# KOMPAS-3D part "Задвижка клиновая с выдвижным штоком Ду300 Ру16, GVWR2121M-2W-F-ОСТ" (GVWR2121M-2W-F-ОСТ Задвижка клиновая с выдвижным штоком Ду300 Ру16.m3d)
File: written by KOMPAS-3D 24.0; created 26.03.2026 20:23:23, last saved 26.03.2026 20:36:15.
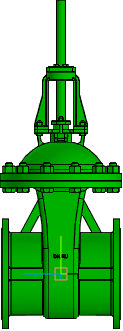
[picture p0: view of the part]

Document properties: Автор: R2D2; Полное имя файла: GVWR2121M-2W-F-ОСТ Задвижка клиновая с видвижным штоком Ду300 Ру16.cdw

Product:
- Part/product: Задвижка клиновая с выдвижным штоком Ду300 Ру16  | designation GVWR2121M-2W-F-ОСТ
    Масса: 210
    Раздел спецификации: Прочие изделия
    Форматы листов документа: A2
    Примечание: D040-07880

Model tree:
1. Операция без истории:1

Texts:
  GVWR2121M-2W-F-ОСТ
